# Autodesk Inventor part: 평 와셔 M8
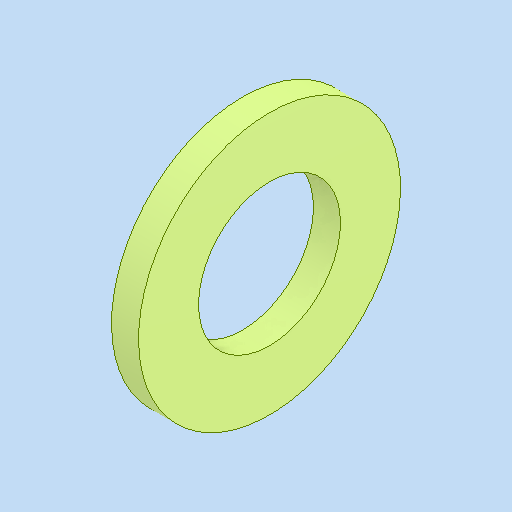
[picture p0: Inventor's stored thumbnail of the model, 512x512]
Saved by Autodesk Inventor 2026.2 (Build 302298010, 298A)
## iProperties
Created: 2026-08
Part Number: 평 와셔 M8
Material: 강철, 연강
Description: 평면 와셔
Document SubType Name: Modeling
Designer: PC2-02
Density: 7.85 g/cm^3
Appearance: 기본값
Author: jhkim
Sending System: Autodesk Inventor 2027
Preprocessor: ST-DEVELOPER v20.1
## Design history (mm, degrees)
feature "Solid1"
node "솔리드1"
